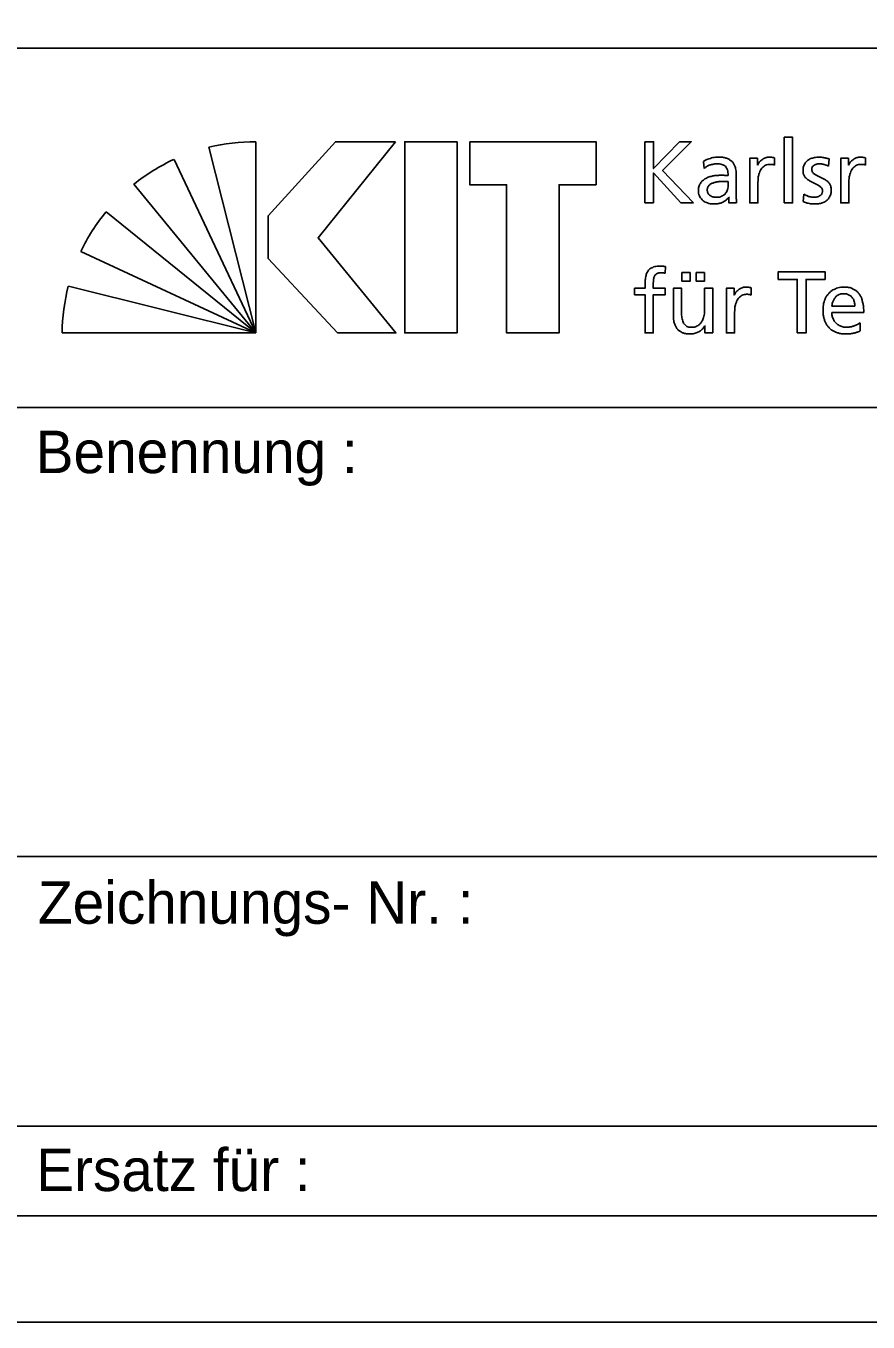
# Model space of a CAD drawing. Extents: x 0 to 238, y 0 to 168.
# Drawn here: x 220.13 to 228.07, y 0 to 12.21 of the extents above; entities that cross this region are included whole.
import ezdxf

# ---------------------------------------------------------------- set-up
doc = ezdxf.new("R2010")
doc.units = 0
doc.layers.add('90_Plankopf', color=7, linetype='Continuous')

msp = doc.modelspace()

# ---------------------------------------------------------------- linework, layer by layer
at = {"layer": '90_Plankopf'}
for p, q in [((201.224, 11.998), (236.8, 11.998)), ((201.224, 11.998), (236.8, 11.998)), ((222.296, 9.317), (222.296, 11.117)), ((225.962, 11.117), (225.962, 10.541)), ((221.855, 11.067), (222.296, 9.317)), ((222.296, 9.317), (221.527, 10.95)), ((226.516, 10.932), (226.52, 10.866)), ((227.185, 10.897), (227.185, 10.966)), ((227.691, 10.888), (227.698, 10.956)), ((228.042, 10.897), (228.042, 10.966)), ((226.824, 10.624), (226.824, 10.798)), ((221.149, 10.717), (222.296, 9.317)), ((226.746, 10.742), (226.746, 10.705)), ((227.459, 10.624), (227.455, 10.554)), ((225.962, 10.541), (226.044, 10.541)), ((226.301, 10.541), (226.422, 10.541)), ((222.296, 9.317), (220.887, 10.457)), ((220.648, 10.083), (222.296, 9.317)), ((226.155, 9.879), (226.158, 9.941)), ((222.296, 9.317), (220.532, 9.758)), ((226.965, 9.673), (226.965, 9.742)), ((227.941, 9.568), (227.723, 9.568)), ((227.723, 9.51), (228.024, 9.51)), ((227.992, 9.335), (227.992, 9.412)), ((220.473, 9.317), (222.296, 9.317)), ((220, 8.614), (236.8, 8.614)), ((220, 4.384), (236.8, 4.384)), ((220, 1.846), (236.8, 1.846)), ((236.8, 1), (201.224, 1)), ((203.56, 1), (236.8, 1)), ((203.56, 1), (236.8, 1))]:
    msp.add_line(p, q, dxfattribs=at)
for points in [[(0, 0), (237.8, 0), (237.8, 168.2), (0, 168.2)], [(5, 1), (236.8, 1), (236.8, 167.2), (5, 167.2)], [(223.613, 11.117), (223.047, 11.117), (222.415, 10.42), (222.415, 10.018), (223.068, 9.317), (223.617, 9.317), (222.884, 10.213)], [(224.194, 11.117), (224.194, 9.317), (223.7, 9.317), (223.7, 11.117)], [(224.312, 11.117), (224.312, 10.712), (224.66, 10.712), (224.66, 9.317), (225.154, 9.317), (225.154, 10.712), (225.502, 10.712), (225.502, 11.117)]]:
    msp.add_lwpolyline(points, close=True, dxfattribs=at)
for points in [[(226.422, 10.541), (226.129, 10.845), (226.4, 11.117), (226.29, 11.117), (226.044, 10.864), (226.044, 11.117), (225.962, 11.117)], [(227.276, 10.541), (227.354, 10.541), (227.354, 11.16), (227.276, 11.16), (227.276, 10.541)], [(227.024, 10.897), (227.023, 10.897), (227.023, 10.962), (226.95, 10.962), (226.95, 10.541), (227.028, 10.541), (227.028, 10.733)], [(227.881, 10.897), (227.88, 10.897), (227.88, 10.962), (227.807, 10.962), (227.807, 10.541), (227.885, 10.541), (227.885, 10.733)], [(226.044, 10.541), (226.044, 10.823), (226.301, 10.541)], [(226.753, 10.596), (226.754, 10.596), (226.754, 10.541), (226.827, 10.541)], [(227.398, 9.317), (227.481, 9.317), (227.481, 9.821), (227.66, 9.821), (227.66, 9.893), (227.219, 9.893), (227.219, 9.821), (227.398, 9.821), (227.398, 9.317)], [(225.965, 9.777), (225.965, 9.738), (225.866, 9.738), (225.866, 9.676), (225.965, 9.676), (225.965, 9.317), (226.042, 9.317), (226.042, 9.676), (226.154, 9.676), (226.154, 9.738), (226.042, 9.738), (226.042, 9.784)], [(226.311, 9.885), (226.311, 9.803), (226.388, 9.803), (226.388, 9.885), (226.311, 9.885)], [(226.446, 9.885), (226.446, 9.803), (226.524, 9.803), (226.524, 9.885), (226.446, 9.885)], [(226.308, 9.52), (226.308, 9.738), (226.231, 9.738), (226.231, 9.488)], [(226.603, 9.317), (226.603, 9.738), (226.525, 9.738), (226.525, 9.543)], [(226.804, 9.673), (226.803, 9.673), (226.803, 9.738), (226.73, 9.738), (226.73, 9.317), (226.808, 9.317), (226.808, 9.509)], [(226.526, 9.384), (226.528, 9.384), (226.528, 9.317), (226.603, 9.317)]]:
    msp.add_lwpolyline(points, dxfattribs=at)
for centre, start, end in [((222.29, 9.211), 89.8053, 103.1895), ((222.332, 9.224), 115.0126, 128.3968), ((222.363, 9.253), 140.7898, 154.174), ((222.378, 9.288), 165.7222, 179.1064)]:
    msp.add_arc(centre, 1.906, start, end, dxfattribs=at)
for points in [[(226.824, 10.798), (226.824, 10.836), (226.818, 10.868), (226.807, 10.894), (226.795, 10.92), (226.777, 10.939), (226.752, 10.952), (226.727, 10.965), (226.694, 10.972), (226.654, 10.972), (226.628, 10.972), (226.603, 10.968), (226.58, 10.961), (226.556, 10.954), (226.535, 10.944), (226.516, 10.932)], [(226.52, 10.866), (226.531, 10.875), (226.543, 10.883), (226.556, 10.889), (226.569, 10.896), (226.583, 10.901), (226.598, 10.904), (226.613, 10.908), (226.627, 10.909), (226.642, 10.909), (226.668, 10.909), (226.688, 10.905), (226.704, 10.897), (226.719, 10.889), (226.73, 10.877), (226.736, 10.86), (226.743, 10.844), (226.746, 10.824), (226.746, 10.799)], [(227.185, 10.966), (227.18, 10.967), (227.175, 10.968), (227.17, 10.969), (227.165, 10.97), (227.16, 10.971), (227.154, 10.971), (227.148, 10.972), (227.142, 10.972), (227.134, 10.972), (227.119, 10.972), (227.105, 10.969), (227.09, 10.962), (227.076, 10.956), (227.064, 10.947), (227.052, 10.936), (227.041, 10.925), (227.031, 10.912), (227.024, 10.897)], [(227.028, 10.733), (227.028, 10.768), (227.033, 10.799), (227.042, 10.824), (227.051, 10.85), (227.065, 10.87), (227.082, 10.883), (227.099, 10.897), (227.119, 10.904), (227.142, 10.904), (227.149, 10.904), (227.156, 10.904), (227.164, 10.903), (227.171, 10.902), (227.178, 10.9), (227.185, 10.897)], [(227.698, 10.956), (227.683, 10.96), (227.667, 10.964), (227.652, 10.967), (227.636, 10.97), (227.619, 10.972), (227.601, 10.972), (227.581, 10.972), (227.561, 10.969), (227.543, 10.964), (227.525, 10.959), (227.509, 10.951), (227.496, 10.94), (227.482, 10.929), (227.472, 10.916), (227.464, 10.9), (227.457, 10.883), (227.453, 10.864), (227.453, 10.842), (227.453, 10.826), (227.456, 10.811), (227.463, 10.799), (227.469, 10.787), (227.478, 10.776), (227.489, 10.767), (227.5, 10.758), (227.512, 10.75), (227.525, 10.743), (227.538, 10.736), (227.551, 10.729), (227.563, 10.723), (227.576, 10.717), (227.588, 10.711), (227.599, 10.704), (227.61, 10.698), (227.619, 10.691), (227.625, 10.683), (227.632, 10.675), (227.635, 10.665), (227.635, 10.654), (227.635, 10.643), (227.633, 10.633), (227.628, 10.626), (227.623, 10.618), (227.617, 10.612), (227.609, 10.607), (227.601, 10.602), (227.593, 10.599), (227.583, 10.597), (227.574, 10.595), (227.565, 10.594), (227.556, 10.594), (227.548, 10.594), (227.539, 10.595), (227.528, 10.597), (227.517, 10.599), (227.505, 10.603), (227.493, 10.607), (227.481, 10.612), (227.47, 10.617), (227.459, 10.624)], [(227.455, 10.554), (227.473, 10.545), (227.492, 10.539), (227.512, 10.536), (227.531, 10.532), (227.551, 10.531), (227.571, 10.531), (227.59, 10.531), (227.608, 10.534), (227.625, 10.539), (227.643, 10.544), (227.659, 10.552), (227.673, 10.563), (227.686, 10.574), (227.697, 10.588), (227.705, 10.604), (227.714, 10.621), (227.718, 10.64), (227.718, 10.662), (227.718, 10.682), (227.714, 10.698), (227.708, 10.711), (227.701, 10.724), (227.692, 10.736), (227.682, 10.745), (227.671, 10.754), (227.659, 10.762), (227.646, 10.769), (227.633, 10.776), (227.62, 10.782), (227.607, 10.787), (227.594, 10.793), (227.582, 10.799), (227.572, 10.805), (227.561, 10.812), (227.552, 10.819), (227.545, 10.827), (227.539, 10.836), (227.536, 10.846), (227.535, 10.858), (227.536, 10.87), (227.539, 10.879), (227.546, 10.887), (227.553, 10.894), (227.562, 10.9), (227.573, 10.904), (227.584, 10.908), (227.596, 10.909), (227.61, 10.909), (227.614, 10.909), (227.62, 10.909), (227.628, 10.908), (227.635, 10.906), (227.643, 10.905), (227.651, 10.903), (227.659, 10.901), (227.667, 10.898), (227.674, 10.896), (227.681, 10.893), (227.687, 10.891), (227.691, 10.888)], [(228.042, 10.966), (228.037, 10.967), (228.032, 10.968), (228.027, 10.969), (228.022, 10.97), (228.017, 10.971), (228.011, 10.971), (228.005, 10.972), (227.999, 10.972), (227.991, 10.972), (227.976, 10.972), (227.962, 10.969), (227.947, 10.962), (227.933, 10.956), (227.921, 10.947), (227.909, 10.936), (227.898, 10.925), (227.888, 10.912), (227.881, 10.897)], [(227.885, 10.733), (227.885, 10.768), (227.89, 10.799), (227.899, 10.824), (227.908, 10.85), (227.922, 10.87), (227.939, 10.883), (227.956, 10.897), (227.976, 10.904), (227.999, 10.904), (228.006, 10.904), (228.013, 10.904), (228.021, 10.903), (228.028, 10.902), (228.035, 10.9), (228.042, 10.897)], [(226.746, 10.799), (226.736, 10.8), (226.727, 10.8), (226.718, 10.801), (226.709, 10.801), (226.7, 10.801), (226.692, 10.801), (226.683, 10.801), (226.674, 10.801), (226.664, 10.801), (226.647, 10.801), (226.63, 10.8), (226.613, 10.797), (226.595, 10.794), (226.577, 10.789), (226.56, 10.783), (226.543, 10.776), (226.528, 10.768), (226.514, 10.757), (226.5, 10.746), (226.489, 10.733), (226.481, 10.718), (226.472, 10.702), (226.468, 10.684), (226.468, 10.662), (226.468, 10.632), (226.475, 10.607), (226.488, 10.588), (226.501, 10.568), (226.519, 10.554), (226.542, 10.545), (226.565, 10.536), (226.592, 10.531), (226.622, 10.531), (226.64, 10.531), (226.656, 10.534), (226.67, 10.538), (226.684, 10.542), (226.697, 10.547), (226.707, 10.554), (226.718, 10.56), (226.727, 10.567), (226.735, 10.575), (226.742, 10.582), (226.748, 10.589), (226.753, 10.596)], [(226.746, 10.705), (226.746, 10.684), (226.742, 10.665), (226.733, 10.648), (226.724, 10.631), (226.711, 10.618), (226.693, 10.609), (226.676, 10.599), (226.654, 10.594), (226.629, 10.594), (226.62, 10.594), (226.611, 10.596), (226.602, 10.598), (226.593, 10.601), (226.584, 10.606), (226.576, 10.611), (226.569, 10.617), (226.562, 10.625), (226.558, 10.633), (226.553, 10.641), (226.551, 10.651), (226.55, 10.662), (226.551, 10.677), (226.554, 10.69), (226.562, 10.699), (226.569, 10.709), (226.578, 10.717), (226.59, 10.723), (226.601, 10.729), (226.614, 10.733), (226.627, 10.736), (226.64, 10.739), (226.653, 10.741), (226.665, 10.742), (226.677, 10.743), (226.688, 10.743), (226.697, 10.743), (226.705, 10.743), (226.713, 10.743), (226.721, 10.743), (226.73, 10.742), (226.738, 10.742), (226.746, 10.742)], [(226.827, 10.541), (226.826, 10.545), (226.826, 10.551), (226.825, 10.557), (226.825, 10.564), (226.824, 10.573), (226.824, 10.584), (226.824, 10.595), (226.824, 10.608), (226.824, 10.624)], [(226.158, 9.941), (226.15, 9.942), (226.142, 9.944), (226.134, 9.945), (226.125, 9.946), (226.116, 9.946), (226.106, 9.946), (226.078, 9.946), (226.054, 9.942), (226.036, 9.934), (226.017, 9.926), (226.003, 9.915), (225.992, 9.9), (225.982, 9.885), (225.975, 9.867), (225.971, 9.847), (225.967, 9.826), (225.965, 9.803), (225.965, 9.777)], [(226.042, 9.784), (226.042, 9.798), (226.043, 9.811), (226.045, 9.823), (226.046, 9.835), (226.05, 9.846), (226.055, 9.855), (226.06, 9.864), (226.068, 9.871), (226.078, 9.876), (226.088, 9.881), (226.101, 9.883), (226.118, 9.883), (226.124, 9.883), (226.131, 9.883), (226.138, 9.882), (226.144, 9.881), (226.15, 9.88), (226.155, 9.879)], [(226.965, 9.742), (226.96, 9.743), (226.955, 9.744), (226.95, 9.745), (226.945, 9.746), (226.94, 9.747), (226.934, 9.747), (226.928, 9.748), (226.922, 9.748), (226.914, 9.748), (226.899, 9.748), (226.885, 9.745), (226.87, 9.738), (226.856, 9.732), (226.844, 9.723), (226.832, 9.712), (226.821, 9.701), (226.811, 9.688), (226.804, 9.673)], [(226.808, 9.509), (226.808, 9.544), (226.813, 9.575), (226.822, 9.6), (226.832, 9.626), (226.845, 9.646), (226.862, 9.659), (226.879, 9.673), (226.899, 9.68), (226.922, 9.68), (226.929, 9.681), (226.936, 9.68), (226.944, 9.679), (226.951, 9.678), (226.958, 9.676), (226.965, 9.673)], [(228.024, 9.51), (228.024, 9.544), (228.021, 9.576), (228.014, 9.605), (228.008, 9.634), (227.998, 9.659), (227.984, 9.68), (227.969, 9.701), (227.95, 9.718), (227.926, 9.73), (227.902, 9.742), (227.873, 9.748), (227.838, 9.748), (227.808, 9.748), (227.781, 9.743), (227.757, 9.732), (227.733, 9.722), (227.712, 9.707), (227.695, 9.688), (227.677, 9.669), (227.664, 9.647), (227.655, 9.621), (227.646, 9.595), (227.641, 9.567), (227.641, 9.535), (227.641, 9.501), (227.645, 9.47), (227.654, 9.442), (227.662, 9.414), (227.676, 9.39), (227.694, 9.37), (227.712, 9.35), (227.734, 9.334), (227.762, 9.324), (227.789, 9.313), (227.821, 9.308), (227.859, 9.307), (227.882, 9.308), (227.901, 9.309), (227.917, 9.312), (227.933, 9.315), (227.947, 9.319), (227.959, 9.323), (227.971, 9.327), (227.982, 9.331), (227.992, 9.335)], [(227.723, 9.568), (227.725, 9.582), (227.728, 9.596), (227.733, 9.609), (227.738, 9.623), (227.744, 9.636), (227.754, 9.647), (227.762, 9.659), (227.774, 9.668), (227.787, 9.675), (227.801, 9.682), (227.817, 9.685), (227.836, 9.685), (227.853, 9.685), (227.868, 9.682), (227.881, 9.676), (227.894, 9.67), (227.905, 9.662), (227.914, 9.651), (227.923, 9.64), (227.93, 9.628), (227.934, 9.614), (227.939, 9.6), (227.941, 9.584), (227.941, 9.568)], [(226.525, 9.543), (226.525, 9.518), (226.523, 9.494), (226.518, 9.473), (226.513, 9.452), (226.505, 9.434), (226.495, 9.418), (226.484, 9.403), (226.471, 9.391), (226.455, 9.383), (226.439, 9.374), (226.419, 9.37), (226.397, 9.37), (226.375, 9.371), (226.357, 9.378), (226.344, 9.389), (226.331, 9.4), (226.322, 9.417), (226.316, 9.439), (226.311, 9.46), (226.308, 9.488), (226.308, 9.52)], [(226.231, 9.488), (226.231, 9.45), (226.236, 9.418), (226.247, 9.391), (226.259, 9.364), (226.276, 9.343), (226.299, 9.329), (226.322, 9.315), (226.352, 9.308), (226.388, 9.307), (226.408, 9.308), (226.427, 9.311), (226.445, 9.317), (226.463, 9.323), (226.479, 9.332), (226.493, 9.343), (226.507, 9.354), (226.518, 9.368), (226.526, 9.384)], [(227.992, 9.412), (227.987, 9.408), (227.98, 9.404), (227.97, 9.399), (227.961, 9.394), (227.951, 9.39), (227.939, 9.385), (227.927, 9.381), (227.914, 9.377), (227.901, 9.374), (227.888, 9.372), (227.875, 9.37), (227.862, 9.37), (227.843, 9.37), (227.826, 9.374), (227.809, 9.38), (227.793, 9.387), (227.778, 9.397), (227.765, 9.409), (227.752, 9.421), (227.742, 9.436), (227.735, 9.453), (227.727, 9.471), (227.723, 9.49), (227.723, 9.51)]]:
    msp.add_open_spline(points, degree=3, dxfattribs=at)

# ---------------------------------------------------------------- texts
for s, p in [('Benennung :', (220.223, 7.996)), ('Zeichnungs- Nr. :', (220.245, 3.752)), ('Ersatz für :', (220.228, 1.234))]:
    msp.add_text(s, height=0.4, dxfattribs=at).set_placement(p)

doc.saveas('drawing.dxf')
